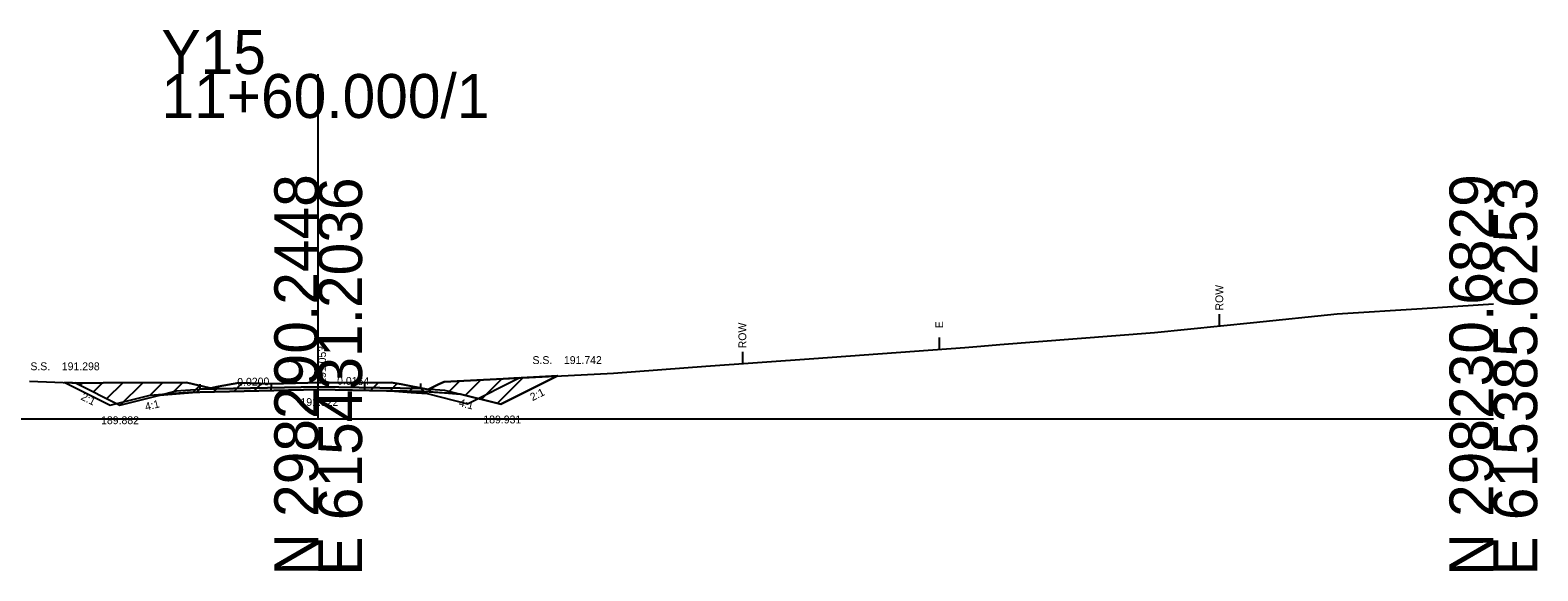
# Model space of a CAD drawing. Extents: x 517327 to 517505, y 114839 to 116885.
# Drawn here: x 517409 to 517505.2, y 115338.7 to 115373.2 of the extents above; entities that cross this region are included whole.
import ezdxf

# ---------------------------------------------------------------- set-up
doc = ezdxf.new("R2010")
doc.units = 0
for name, color, linetype in [('Exist XS Ground Line', 7, 'Continuous'), ('Old_Level_60', 7, 'Continuous'), ('Old_Level_63', 7, 'Continuous'), ('Prop XS Dump Level', 7, 'Continuous'), ('Prop XS Earthwork Shape', 7, 'Continuous'), ('Prop XS Elevation Labels', 7, 'Continuous'), ('Prop XS EOT Tick Mark', 7, 'Continuous'), ('Prop XS Exc Vertical Line 1', 7, 'Continuous'), ('Prop XS Exc Vertical Line 2', 7, 'Continuous'), ('Prop XS Finish Grade', 7, 'Continuous'), ('Prop XS Finish Grade Earthwork', 7, 'Continuous'), ('Prop XS Finish Grade Pavement', 7, 'Continuous'), ('Prop XS Hydro Elevations', 7, 'Continuous'), ('Prop XS Label Text', 7, 'Continuous'), ('Prop XS Pvmt Edge Slope', 7, 'Continuous'), ('Prop XS SE Text', 7, 'Continuous'), ('Prop XS Side Slope Text', 7, 'Continuous'), ('Prop XS Subgrade Earthwork', 7, 'Continuous'), ('Prop XS Suitable Common Exc Shape', 7, 'Continuous'), ('Scratch_Level_0', 7, 'Continuous')]:
    doc.layers.add(name, color=color, linetype=linetype)

msp = doc.modelspace()

# ---------------------------------------------------------------- linework, layer by layer
at = {"layer": 'Exist XS Ground Line'}
for p, q in [((517492.403, 115355.057), (517497.82, 115355.4)), ((517497.82, 115355.4), (517502.365, 115355.697)), ((517480.747, 115353.884), (517487.056, 115354.519)), ((517487.056, 115354.519), (517492.403, 115355.057)), ((517470.87, 115353.099), (517480.747, 115353.884)), ((517452.107, 115351.731), (517459.003, 115352.207)), ((517459.003, 115352.207), (517468.626, 115352.923)), ((517468.626, 115352.923), (517469.655, 115353.002)), ((517469.655, 115353.002), (517470.87, 115353.099)), ((517439.179, 115350.929), (517446.206, 115351.289)), ((517446.206, 115351.289), (517452.107, 115351.731)), ((517408.936, 115350.767), (517412.176, 115350.652)), ((517412.176, 115350.652), (517413.645, 115350.656)), ((517413.645, 115350.656), (517418.958, 115350.691)), ((517418.958, 115350.691), (517420.489, 115350.327)), ((517420.489, 115350.327), (517420.977, 115350.427)), ((517420.977, 115350.427), (517422.292, 115350.665)), ((517422.292, 115350.665), (517424.378, 115350.605)), ((517424.378, 115350.605), (517427.459, 115350.689)), ((517427.459, 115350.689), (517430.289, 115350.66)), ((517430.289, 115350.66), (517432.023, 115350.683)), ((517432.023, 115350.683), (517432.653, 115350.575)), ((517432.653, 115350.575), (517434.379, 115350.242)), ((517434.379, 115350.242), (517435.064, 115350.586)), ((517435.064, 115350.586), (517435.407, 115350.726)), ((517435.407, 115350.726), (517439.179, 115350.929))]:
    msp.add_line(p, q, dxfattribs=at)
at = {"layer": 'Old_Level_63'}
for p, q in [((517427.365, 115348.365), (517427.365, 115370.361)), ((517352.365, 115348.365), (517427.365, 115348.365)), ((517427.365, 115348.365), (517502.365, 115348.365))]:
    msp.add_line(p, q, dxfattribs=at)
at = {"layer": 'Prop XS Dump Level'}
for p, q in [((517419.8, 115350.267), (517427.365, 115350.418)), ((517427.365, 115350.418), (517433.924, 115350.311))]:
    msp.add_line(p, q, dxfattribs=at)
at = {"layer": 'Prop XS Earthwork Shape'}
msp.add_lwpolyline([(517411.869, 115350.663), (517414.7, 115349.247), (517417.251, 115349.885), (517418.3, 115349.968), (517419.607, 115350.073), (517419.8, 115350.077), (517427.365, 115350.228), (517433.924, 115350.121), (517434.117, 115350.118), (517435.424, 115350.018), (517436.451, 115349.939), (517439.024, 115349.296), (517442.644, 115351.107), (517439.179, 115350.929), (517435.407, 115350.726), (517435.064, 115350.586), (517434.379, 115350.242), (517432.653, 115350.575), (517432.023, 115350.683), (517430.289, 115350.66), (517427.459, 115350.689), (517424.378, 115350.605), (517422.292, 115350.665), (517420.977, 115350.427), (517420.489, 115350.327), (517418.958, 115350.691), (517413.645, 115350.656), (517412.176, 115350.652)], close=True, dxfattribs=at)
at = {"layer": 'Prop XS EOT Tick Mark'}
for p, q in [((517419.8, 115350.572), (517419.8, 115350.267)), ((517433.924, 115350.311), (517433.924, 115350.616))]:
    msp.add_line(p, q, dxfattribs=at)
at = {"layer": 'Prop XS Exc Vertical Line 1'}
msp.add_line((517466.999, 115353.552), (517466.999, 115352.802), dxfattribs=at)
at = {"layer": 'Prop XS Exc Vertical Line 2'}
for p, q in [((517484.873, 115355.049), (517484.873, 115354.299)), ((517454.435, 115352.642), (517454.435, 115351.892))]:
    msp.add_line(p, q, dxfattribs=at)
at = {"layer": 'Prop XS Finish Grade'}
for p, q in [((517433.924, 115350.311), (517435.424, 115350.196)), ((517417.251, 115349.885), (517418.3, 115350.147)), ((517418.3, 115350.147), (517419.8, 115350.267)), ((517435.424, 115350.196), (517436.451, 115349.939))]:
    msp.add_line(p, q, dxfattribs=at)
at = {"layer": 'Prop XS Finish Grade Earthwork'}
for p, q in [((517411.869, 115350.663), (517414.7, 115349.247)), ((517439.024, 115349.296), (517442.644, 115351.107)), ((517414.7, 115349.247), (517417.251, 115349.885)), ((517436.451, 115349.939), (517439.024, 115349.296))]:
    msp.add_line(p, q, dxfattribs=at)
at = {"layer": 'Prop XS Finish Grade Pavement'}
for p, q in [((517427.365, 115350.418), (517419.8, 115350.267)), ((517433.924, 115350.311), (517427.365, 115350.418))]:
    msp.add_line(p, q, dxfattribs=at)
at = {"layer": 'Prop XS Pvmt Edge Slope'}
for p, q in [((517433.924, 115350.311), (517434.117, 115350.118)), ((517419.607, 115350.073), (517419.8, 115350.267))]:
    msp.add_line(p, q, dxfattribs=at)
at = {"layer": 'Prop XS Subgrade Earthwork'}
for p, q in [((517417.251, 115349.885), (517418.3, 115349.968)), ((517418.3, 115349.968), (517419.607, 115350.073)), ((517419.607, 115350.073), (517419.8, 115350.077)), ((517427.365, 115350.228), (517419.8, 115350.077)), ((517433.924, 115350.121), (517427.365, 115350.228)), ((517433.924, 115350.121), (517434.117, 115350.118)), ((517434.117, 115350.118), (517435.424, 115350.018)), ((517435.424, 115350.018), (517436.451, 115349.939))]:
    msp.add_line(p, q, dxfattribs=at)
at = {"layer": 'Prop XS Suitable Common Exc Shape'}
msp.add_lwpolyline([(517436.888, 115349.331), (517440.187, 115350.981), (517439.179, 115350.929), (517435.407, 115350.726), (517435.064, 115350.586), (517434.379, 115350.242), (517432.653, 115350.575), (517432.023, 115350.683), (517430.289, 115350.66), (517427.459, 115350.689), (517424.378, 115350.605), (517422.292, 115350.665), (517420.977, 115350.427), (517420.489, 115350.327), (517418.958, 115350.691), (517413.645, 115350.656), (517412.176, 115350.652), (517411.184, 115350.687), (517414.089, 115349.235), (517416.64, 115349.872), (517417.689, 115349.956), (517418.995, 115350.061), (517419.189, 115350.065), (517427.365, 115350.228), (517431.788, 115350.156), (517431.981, 115350.153), (517433.288, 115350.053), (517434.315, 115349.974)], close=True, dxfattribs=at)
at = {"layer": 'Scratch_Level_0'}
for p, q in [((517412.182, 115350.506), (517412.328, 115350.652)), ((517413.031, 115350.082), (517413.605, 115350.656)), ((517413.879, 115349.657), (517414.886, 115350.665)), ((517414.755, 115349.26), (517416.167, 115350.673)), ((517416.64, 115349.872), (517417.449, 115350.681)), ((517418.023, 115349.983), (517418.73, 115350.69)), ((517419.381, 115350.068), (517419.803, 115350.49)), ((517420.68, 115350.094), (517421.02, 115350.435)), ((517421.979, 115350.12), (517422.517, 115350.659)), ((517423.278, 115350.146), (517423.754, 115350.623)), ((517430.696, 115350.174), (517431.194, 115350.672)), ((517431.948, 115350.153), (517432.411, 115350.616)), ((517433.201, 115350.133), (517433.483, 115350.415)), ((517434.434, 115350.093), (517434.788, 115350.448)), ((517435.617, 115350.003), (517436.393, 115350.779)), ((517436.751, 115349.864), (517437.738, 115350.852)), ((517437.769, 115349.61), (517439.083, 115350.924)), ((517438.787, 115349.355), (517440.425, 115350.993))]:
    msp.add_line(p, q, dxfattribs=at)
for points in [[(517411.869, 115350.663), (517414.7, 115349.247), (517417.251, 115349.885), (517418.3, 115349.968), (517419.607, 115350.073), (517424.365, 115350.168), (517424.378, 115350.605), (517422.292, 115350.665), (517420.977, 115350.427), (517420.489, 115350.327), (517418.958, 115350.691), (517413.645, 115350.656), (517412.176, 115350.652)], [(517442.644, 115351.107), (517439.024, 115349.296), (517436.451, 115349.939), (517434.117, 115350.118), (517431.981, 115350.153), (517430.34, 115350.179), (517430.34, 115350.66), (517432.023, 115350.683), (517432.653, 115350.575), (517434.379, 115350.242), (517435.064, 115350.586), (517435.407, 115350.726), (517439.179, 115350.929)]]:
    msp.add_lwpolyline(points, close=True, dxfattribs=at)

# ---------------------------------------------------------------- texts
at = {"layer": 'Old_Level_60'}
msp.add_text('191.322', height=0.5, dxfattribs=at).set_placement((517426.233, 115349.186))
at = {"layer": 'Old_Level_63'}
for s, p in [('Y15', (517417.362, 115370.361)), ('11+60.000/1', (517417.364, 115367.561))]:
    msp.add_text(s, height=2.8, dxfattribs=at).set_placement(p)
for s, p in [('N 298290.2448', (517427.365, 115338.365)), ('N 298230.6829', (517502.365, 115338.364)), ('E 615431.2036', (517430.165, 115338.364)), ('E 615385.6253', (517505.165, 115338.365))]:
    msp.add_text(s, height=2.8, rotation=90, dxfattribs=at).set_placement(p)
at = {"layer": 'Prop XS Dump Level'}
for p in [(517418.3, 115350.135), (517435.424, 115350.184)]:
    msp.add_text('Case1', height=0.0122, dxfattribs=at).set_placement(p)
at = {"layer": 'Prop XS Elevation Labels'}
msp.add_text(' 191.053', height=0.5, rotation=90, dxfattribs=at).set_placement((517427.865, 115350.418))
at = {"layer": 'Prop XS Exc Vertical Line 1'}
msp.add_text('E', height=0.5, rotation=90, dxfattribs=at).set_placement((517467.249, 115354.144))
at = {"layer": 'Prop XS Exc Vertical Line 2'}
for p in [(517485.123, 115355.274), (517454.685, 115352.867)]:
    msp.add_text('ROW', height=0.5, rotation=90, dxfattribs=at).set_placement(p)
at = {"layer": 'Prop XS Hydro Elevations'}
for s, p in [('S.S.    191.742', (517441.041, 115351.865)), ('S.S.    191.298', (517408.995, 115351.468))]:
    msp.add_text(s, height=0.5, dxfattribs=at).set_placement(p)
at = {"layer": 'Prop XS Label Text'}
for rotation, p in [(14.03624, (517416.377, 115348.885)), (345.96376, (517436.31, 115349.181))]:
    msp.add_text('4:1', height=0.5, rotation=rotation, dxfattribs=at).set_placement(p)
at = {"layer": 'Prop XS SE Text'}
for s, rotation, p in [('0.0200', 1.14576, (517422.204, 115350.467)), ('0.0164', 359.06254, (517428.567, 115350.551))]:
    msp.add_text(s, height=0.5, rotation=rotation, dxfattribs=at).set_placement(p)
at = {"layer": 'Prop XS Side Slope Text'}
for rotation, p in [(26.56505, (517441.04, 115349.487)), (333.43495, (517412.175, 115349.617))]:
    msp.add_text('2:1', height=0.5, rotation=rotation, dxfattribs=at).set_placement(p)
for s, p in [('189.882', (517413.509, 115348.027)), ('189.931', (517437.905, 115348.076))]:
    msp.add_text(s, height=0.5, dxfattribs=at).set_placement(p)

doc.saveas('drawing.dxf')
